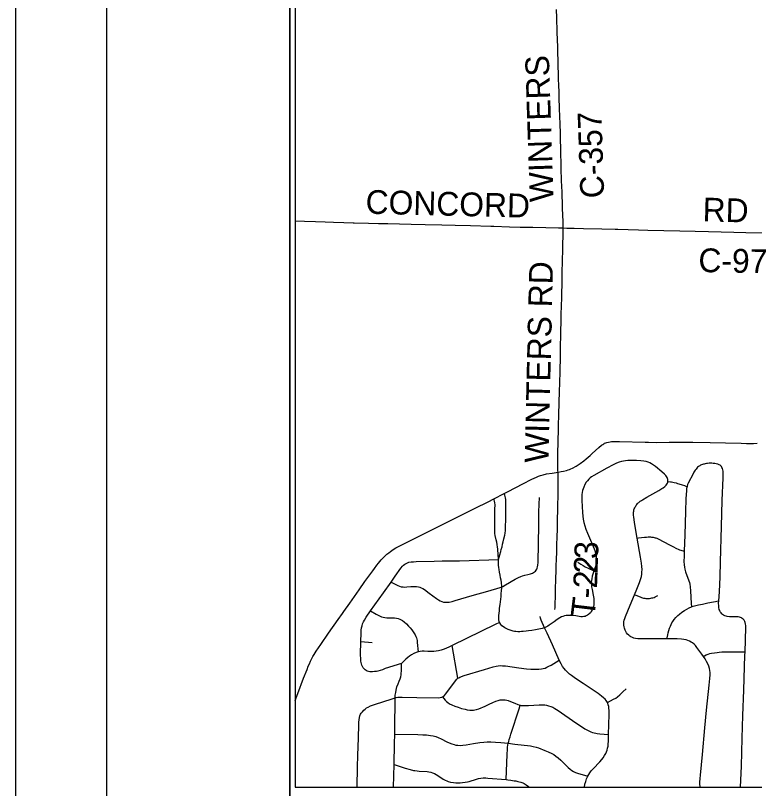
# Model space of a CAD drawing. Extents: x 1341221 to 1914484, y 79347 to 658398.
# Drawn here: x 1341221 to 1359400, y 580393 to 599399 of the extents above; entities that cross this region are included whole.
import ezdxf

# ---------------------------------------------------------------- set-up
doc = ezdxf.new("R2010")
doc.units = 0
for name, color, linetype in [('GM_X_Major_Lake_Text', 7, 'Continuous'), ('GM_X_Major_River_Text', 7, 'Continuous'), ('GM_X_Minor_Lake_Text', 7, 'Continuous'), ('GM_X_Minor_River_Text', 7, 'Continuous'), ('GM_X_State_Location', 7, 'Continuous'), ('GM_X_Township_Text', 7, 'Continuous'), ('GM_X_US_Shield', 7, 'Continuous')]:
    doc.layers.add(name, color=color, linetype=linetype)

msp = doc.modelspace()

# ---------------------------------------------------------------- linework, layer by layer
at = {"layer": 'GM_X_Minor_Lake_Text'}
for points in [[(1343471, 656148), (1347971, 656148), (1347971, 561648), (1343471, 561648)], [(1347971, 656148), (1491971, 656148), (1491971, 561648), (1347971, 561648)], [(1435650, 641695), (1348099, 641695), (1348099, 580425), (1435650, 580425)]]:
    msp.add_lwpolyline(points, close=True, dxfattribs=at)
at = {"layer": 'GM_X_Minor_River_Text'}
msp.add_lwpolyline([(1341221, 559398), (1494221, 559398), (1494221, 658398), (1341221, 658398)], close=True, dxfattribs=at)
at = {"layer": 'GM_X_State_Location'}
for points in [[(1349263, 584696), (1349300, 584748), (1349446, 584954), (1349675, 585278), (1349818, 585479), (1350009, 585745), (1350052, 585804), (1350111, 585884), (1350148, 585932), (1350181, 585974), (1350214, 586013), (1350245, 586048), (1350270, 586073), (1350305, 586108), (1350342, 586140), (1350359, 586155), (1350382, 586174), (1350402, 586189), (1350442, 586221), (1350510, 586267), (1350576, 586307), (1350626, 586335), (1351393, 586721), (1352005, 587022), (1352364, 587201), (1352525, 587284), (1352845, 587444), (1352989, 587517), (1353241, 587647), (1353340, 587698), (1353697, 587884), (1353921, 587997), (1354038, 588051), (1354089, 588072), (1354137, 588090), (1354197, 588107), (1354285, 588127), (1354422, 588149), (1354568, 588172), (1354646, 588184), (1354700, 588195), (1354775, 588213), (1354814, 588225), (1354850, 588238), (1354881, 588252), (1354924, 588272), (1355011, 588320), (1355107, 588383), (1355202, 588453), (1355262, 588502), (1355304, 588537), (1355358, 588584), (1355406, 588630), (1355566, 588775), (1355633, 588831), (1355665, 588854), (1355693, 588870), (1355712, 588880), (1355743, 588893), (1355766, 588901), (1355810, 588912), (1355845, 588918), (1355880, 588922), (1355962, 588924), (1356080, 588923), (1356707, 588906), (1356794, 588905), (1356981, 588904), (1357301, 588908), (1357570, 588908), (1357883, 588907), (1358306, 588899), (1358683, 588893), (1359067, 588883), (1359201, 588879), (1359374, 588877), (1359468, 588880)], [(1348099, 582561), (1348163, 582726), (1348308, 583102), (1348392, 583323), (1348424, 583402), (1348449, 583460), (1348478, 583521), (1348503, 583572), (1348537, 583636), (1348569, 583691), (1348620, 583772), (1348728, 583937), (1348918, 584209), (1349157, 584547), (1349263, 584696)]]:
    msp.add_lwpolyline(points, dxfattribs=at)
at = {"layer": 'GM_X_Township_Text'}
for p, q in [((1349718, 584004), (1349992, 583983)), ((1352100, 583103), (1351960, 583907))]:
    msp.add_line(p, q, dxfattribs=at)
for points in [[(1354568, 588172), (1354565, 588206), (1354561, 588243), (1354560, 588261), (1354560, 588275), (1354559, 588315), (1354559, 588347), (1354559, 588394), (1354561, 588470), (1354562, 588555), (1354564, 588656), (1354569, 588894), (1354571, 588996), (1354575, 589150), (1354581, 589377), (1354584, 589519), (1354588, 589657), (1354593, 589807), (1354597, 589956), (1354600, 590076), (1354604, 590199), (1354608, 590319), (1354613, 590465), (1354615, 590550), (1354619, 590668), (1354621, 590762), (1354624, 590903), (1354625, 591024), (1354627, 591145), (1354628, 591233), (1354630, 591319), (1354634, 591484), (1354637, 591613), (1354638, 591651), (1354644, 591855), (1354647, 592021), (1354653, 592284), (1354656, 592434), (1354659, 592583), (1354664, 592786), (1354667, 592949), (1354671, 593136), (1354674, 593301), (1354676, 593397), (1354681, 593616), (1354685, 593765), (1354689, 593991), (1354690, 594074), (1354693, 594175)], [(1358065, 580425), (1358061, 580446), (1358055, 580498), (1358054, 580550), (1358059, 580640), (1358068, 580723), (1358117, 581232), (1358179, 581882), (1358221, 582321), (1358286, 582938), (1358301, 583095), (1358306, 583185), (1358306, 583249), (1358300, 583297), (1358291, 583342), (1358272, 583402), (1358248, 583461), (1358221, 583518), (1358186, 583578), (1358145, 583640), (1358103, 583699), (1357983, 583864), (1357946, 583907), (1357911, 583943), (1357877, 583971), (1357839, 583994), (1357801, 584015), (1357755, 584034), (1357715, 584045), (1357664, 584055), (1357601, 584063), (1357493, 584069), (1357248, 584070), (1357052, 584071), (1356700, 584070), (1356611, 584069), (1356527, 584074), (1356475, 584081), (1356431, 584091), (1356394, 584104), (1356358, 584121), (1356330, 584139), (1356304, 584160), (1356277, 584189), (1356253, 584220), (1356232, 584253), (1356215, 584289), (1356199, 584332), (1356190, 584370), (1356185, 584409), (1356184, 584448), (1356187, 584487), (1356195, 584532), (1356208, 584576), (1356226, 584625), (1356343, 584902), (1356450, 585157), (1356506, 585291), (1356572, 585462), (1356595, 585531), (1356616, 585608), (1356625, 585659), (1356630, 585715), (1356632, 585778), (1356628, 585854), (1356619, 585937), (1356598, 586082), (1356516, 586550), (1356457, 586882), (1356438, 586996), (1356427, 587076), (1356425, 587108), (1356423, 587133), (1356424, 587163), (1356425, 587190), (1356429, 587215), (1356434, 587242), (1356442, 587266), (1356454, 587294), (1356466, 587319), (1356477, 587338), (1356491, 587359), (1356505, 587378), (1356522, 587398), (1356540, 587417), (1356552, 587428), (1356571, 587444), (1356588, 587457), (1356618, 587477), (1356644, 587494), (1356748, 587552), (1357043, 587718), (1357123, 587770), (1357148, 587789), (1357191, 587822), (1357222, 587850), (1357244, 587879), (1357257, 587903), (1357264, 587922), (1357267, 587940), (1357267, 587968), (1357265, 587989), (1357260, 588013), (1357251, 588038), (1357238, 588062), (1357218, 588086), (1357188, 588118), (1357122, 588178), (1356966, 588310), (1356918, 588345), (1356867, 588377), (1356824, 588400), (1356779, 588417), (1356735, 588430), (1356680, 588442), (1356602, 588451), (1356495, 588455), (1356378, 588457), (1356284, 588455), (1356229, 588451), (1356178, 588443), (1356124, 588432), (1356070, 588415), (1356003, 588388), (1355923, 588350), (1355765, 588266), (1355445, 588091), (1355392, 588057), (1355357, 588030), (1355321, 587995), (1355289, 587957), (1355262, 587921), (1355228, 587864), (1355199, 587804), (1355183, 587762), (1355169, 587718), (1355160, 587673), (1355154, 587623), (1355151, 587566), (1355151, 587471), (1355156, 587323), (1355165, 587176), (1355172, 587088), (1355183, 587012), (1355200, 586932), (1355222, 586852), (1355250, 586768), (1355290, 586667), (1355416, 586380), (1355470, 586242), (1355488, 586187), (1355501, 586130), (1355508, 586085), (1355511, 586040), (1355509, 585994), (1355505, 585949), (1355495, 585891), (1355484, 585855), (1355447, 585741), (1355429, 585685), (1355408, 585612), (1355394, 585550), (1355388, 585506), (1355385, 585456), (1355386, 585393), (1355390, 585355), (1355402, 585287), (1355432, 585143), (1355444, 585066), (1355448, 585009), (1355449, 584956), (1355445, 584913), (1355437, 584868), (1355423, 584823), (1355406, 584786), (1355384, 584746), (1355361, 584716), (1355333, 584686), (1355313, 584668), (1355288, 584651), (1355258, 584636), (1355231, 584626), (1355201, 584620), (1355164, 584616), (1355129, 584617), (1355087, 584622), (1355005, 584636), (1354936, 584645), (1354867, 584650), (1354818, 584649), (1354769, 584644), (1354725, 584636), (1354685, 584625), (1354654, 584612), (1354611, 584590), (1354546, 584547), (1354467, 584490), (1354348, 584406), (1354313, 584384), (1354279, 584365), (1354236, 584342)], [(1359053, 580425), (1359078, 580939), (1359098, 581628), (1359115, 582190), (1359139, 582815), (1359162, 583670), (1359165, 583749), (1359187, 584352), (1359186, 584397), (1359180, 584434), (1359170, 584471), (1359157, 584501), (1359141, 584528), (1359118, 584556), (1359098, 584575), (1359077, 584588), (1359053, 584599), (1359031, 584606), (1358998, 584611), (1358947, 584612), (1358903, 584612), (1358781, 584617), (1358730, 584622), (1358699, 584629), (1358665, 584640), (1358637, 584654), (1358614, 584669), (1358594, 584687), (1358575, 584710), (1358556, 584737), (1358544, 584766), (1358533, 584797), (1358524, 584840), (1358519, 584885), (1358516, 584949), (1358520, 585010), (1358536, 585230), (1358550, 585600), (1358565, 585969), (1358588, 586832), (1358607, 587472), (1358627, 588034), (1358627, 588150), (1358625, 588192), (1358618, 588232), (1358610, 588259), (1358599, 588283), (1358584, 588306), (1358569, 588325), (1358551, 588341), (1358529, 588354), (1358496, 588368), (1358455, 588378), (1358422, 588383), (1358384, 588387), (1358350, 588389), (1358314, 588389), (1358280, 588388), (1358246, 588385), (1358216, 588381), (1358189, 588377), (1358164, 588371), (1358143, 588366), (1358123, 588361), (1358097, 588351), (1358074, 588341), (1358051, 588327), (1358025, 588311), (1358000, 588290), (1357982, 588271), (1357962, 588248), (1357937, 588219), (1357923, 588196), (1357906, 588168), (1357887, 588132), (1357766, 587898), (1357752, 587865), (1357739, 587816), (1357729, 587770), (1357723, 587721), (1357711, 587514), (1357700, 587201), (1357682, 586626), (1357669, 586232), (1357665, 586109), (1357663, 585974), (1357667, 585892), (1357673, 585834), (1357682, 585784), (1357700, 585723), (1357787, 585496), (1357799, 585458), (1357809, 585416), (1357818, 585353), (1357825, 585251), (1357841, 584945), (1357846, 584862)], [(1354491, 584796), (1354493, 584841), (1354495, 584901), (1354498, 584980), (1354500, 585065), (1354502, 585159), (1354503, 585231), (1354507, 585350), (1354511, 585486), (1354514, 585584), (1354518, 585717), (1354523, 585874), (1354527, 586026), (1354533, 586208), (1354539, 586387), (1354544, 586579), (1354550, 586768), (1354553, 586894), (1354556, 587032), (1354560, 587221), (1354563, 587367), (1354567, 587584), (1354570, 587744), (1354571, 587890), (1354571, 588044), (1354571, 588075), (1354571, 588112), (1354570, 588136), (1354569, 588154), (1354568, 588172)], [(1357267, 587940), (1357329, 587935), (1357357, 587931), (1357389, 587926), (1357422, 587919), (1357472, 587905), (1357503, 587896), (1357539, 587885), (1357618, 587857), (1357673, 587839), (1357722, 587822), (1357739, 587816)], [(1350462, 585469), (1350623, 585383), (1350668, 585365), (1350711, 585354), (1350755, 585348), (1350795, 585346), (1350847, 585349), (1350947, 585357), (1351029, 585360), (1351088, 585358), (1351133, 585351), (1351166, 585343), (1351200, 585330), (1351239, 585310), (1351278, 585286), (1351397, 585199), (1351575, 585065), (1351627, 585028), (1351668, 585007), (1351710, 584989), (1351752, 584977), (1351790, 584972), (1351842, 584971), (1351887, 584976), (1351965, 584994), (1352032, 585012), (1352455, 585137), (1352843, 585248), (1353145, 585333), (1353182, 585349), (1353207, 585361), (1353272, 585398), (1353510, 585536), (1353590, 585578), (1353647, 585604), (1353691, 585620), (1353748, 585635), (1353823, 585652), (1353892, 585671), (1353937, 585687), (1353965, 585700), (1353991, 585718), (1354015, 585740), (1354030, 585761), (1354044, 585783), (1354055, 585811), (1354063, 585844), (1354070, 585882), (1354074, 585947), (1354086, 586413), (1354091, 586867), (1354097, 587187), (1354103, 587385), (1354110, 587544)], [(1353105, 586021), (1353099, 586062), (1353096, 586119), (1353093, 586176), (1353088, 586238), (1353085, 586284), (1353080, 586329), (1353070, 586390), (1353058, 586446), (1353045, 586509), (1353022, 586611), (1353015, 586661), (1353012, 586697), (1353009, 586840), (1353010, 587073), (1353012, 587187), (1353014, 587262), (1353016, 587366), (1353012, 587418), (1353006, 587458), (1352997, 587489), (1352989, 587517)], [(1353105, 586021), (1353136, 586142), (1353156, 586217), (1353169, 586268), (1353189, 586338), (1353203, 586397), (1353219, 586456), (1353237, 586530), (1353260, 586624), (1353267, 586674), (1353273, 586739), (1353276, 586795), (1353281, 587040), (1353283, 587254), (1353285, 587404), (1353282, 587501), (1353278, 587536), (1353269, 587573), (1353256, 587609), (1353241, 587647)], [(1356516, 586550), (1356544, 586553), (1356692, 586572), (1356740, 586575), (1356786, 586578), (1356816, 586578), (1356842, 586577), (1356864, 586576), (1356885, 586574), (1356909, 586570), (1356933, 586565), (1356956, 586560), (1356975, 586555), (1356996, 586546), (1357030, 586529), (1357310, 586385), (1357389, 586344), (1357480, 586297), (1357521, 586277), (1357553, 586263), (1357584, 586252), (1357611, 586244), (1357641, 586238), (1357669, 586232)], [(1353130, 584477), (1353020, 584423), (1351960, 583907), (1351881, 583871), (1351763, 583822), (1351691, 583797), (1351624, 583778), (1351569, 583767), (1351512, 583761), (1351456, 583759), (1351367, 583763), (1351270, 583768), (1351221, 583767), (1351175, 583762), (1351128, 583754), (1351075, 583735), (1351016, 583710), (1350963, 583682), (1350914, 583651), (1350872, 583618), (1350826, 583576), (1350789, 583539), (1350748, 583499), (1350712, 583470), (1350318, 583340), (1350246, 583315), (1350189, 583297), (1350136, 583282), (1350100, 583274), (1350051, 583266), (1350004, 583260), (1349968, 583260), (1349936, 583264), (1349902, 583270), (1349874, 583279), (1349848, 583292), (1349820, 583311), (1349794, 583334), (1349772, 583360), (1349754, 583393), (1349739, 583426), (1349728, 583462), (1349722, 583490), (1349717, 583523), (1349713, 583573), (1349710, 583686), (1349718, 584004), (1349721, 584210), (1349726, 584286), (1349733, 584342), (1349745, 584392), (1349759, 584438), (1349779, 584489), (1349802, 584534), (1349844, 584604), (1349955, 584763), (1350276, 585208), (1350462, 585469), (1350559, 585612), (1350698, 585810), (1350738, 585858), (1350768, 585887), (1350799, 585911), (1350828, 585929), (1350860, 585942), (1350900, 585954), (1350950, 585963), (1351009, 585970), (1351076, 585974), (1351516, 585985), (1351714, 585987), (1352142, 585990), (1353105, 586021)], [(1355213, 580425), (1355213, 580426), (1355228, 580502), (1355247, 580568), (1355268, 580628), (1355296, 580693), (1355322, 580740), (1355346, 580778), (1355384, 580828), (1355430, 580881), (1355594, 581051), (1355641, 581104), (1355677, 581151), (1355712, 581205), (1355738, 581253), (1355757, 581299), (1355771, 581334), (1355786, 581384), (1355796, 581432), (1355802, 581480), (1355806, 581557), (1355811, 581724), (1355822, 582216), (1355822, 582312), (1355817, 582372), (1355812, 582413), (1355803, 582453), (1355790, 582489), (1355782, 582508), (1355766, 582534), (1355749, 582560), (1355723, 582590), (1355687, 582625), (1355637, 582666), (1355553, 582725), (1355187, 582972), (1355043, 583068), (1354959, 583126), (1354895, 583170), (1354846, 583208), (1354804, 583246), (1354751, 583301), (1354715, 583345), (1354680, 583394), (1354641, 583462), (1354598, 583548), (1354432, 583928), (1354300, 584213), (1354236, 584342), (1354172, 584324), (1354096, 584309), (1354013, 584294), (1353925, 584281), (1353843, 584270), (1353781, 584262), (1353712, 584254), (1353667, 584250), (1353630, 584248), (1353575, 584247), (1353529, 584250), (1353496, 584254), (1353459, 584262), (1353415, 584275), (1353336, 584305), (1353260, 584341), (1353221, 584366), (1353186, 584395), (1353159, 584425), (1353134, 584464), (1353130, 584477), (1353120, 584502), (1353113, 584541), (1353111, 584594), (1353114, 584650), (1353119, 584701), (1353124, 584759), (1353130, 584824), (1353142, 584920), (1353150, 584982), (1353164, 585117), (1353171, 585179), (1353178, 585265), (1353181, 585318), (1353182, 585349), (1353182, 585361), (1353180, 585395), (1353178, 585427), (1353174, 585460), (1353165, 585515), (1353154, 585571), (1353140, 585641), (1353127, 585709), (1353116, 585779), (1353110, 585830), (1353104, 585882), (1353103, 585933), (1353105, 586021)], [(1355055, 585957), (1355128, 585907), (1355184, 585872), (1355237, 585841), (1355306, 585807), (1355447, 585741)], [(1356450, 585157), (1356476, 585147), (1356588, 585103), (1356616, 585092), (1356642, 585083), (1356671, 585075), (1356697, 585070), (1356728, 585067), (1356755, 585066), (1356785, 585066), (1356813, 585068), (1356849, 585073), (1356874, 585077), (1356898, 585084), (1356928, 585093), (1356958, 585105), (1356992, 585122), (1357021, 585140)], [(1357248, 584070), (1357253, 584097), (1357266, 584170), (1357279, 584222), (1357292, 584276), (1357311, 584338), (1357331, 584387), (1357349, 584427), (1357367, 584464), (1357387, 584499), (1357423, 584552), (1357464, 584601), (1357515, 584650), (1357553, 584683), (1357615, 584729), (1357673, 584769), (1357733, 584805), (1357789, 584836), (1357846, 584862), (1357889, 584876), (1357925, 584886), (1358024, 584908), (1358123, 584929), (1358252, 584956), (1358388, 584984), (1358439, 584994), (1358507, 585007), (1358520, 585010)], [(1349955, 584763), (1350094, 584682), (1350173, 584641), (1350225, 584618), (1350268, 584604), (1350310, 584595), (1350352, 584590), (1350414, 584589), (1350490, 584591), (1350547, 584589), (1350597, 584582), (1350635, 584573), (1350674, 584560), (1350709, 584543), (1350742, 584522), (1350781, 584492), (1350836, 584442), (1350891, 584388), (1350933, 584342), (1350969, 584296), (1351021, 584223), (1351053, 584170), (1351069, 584134), (1351083, 584098), (1351092, 584066), (1351098, 584028), (1351104, 583982), (1351128, 583754)], [(1354236, 584342), (1354155, 584535), (1354137, 584583), (1354123, 584624)], [(1358145, 583640), (1358169, 583653), (1358210, 583676), (1358257, 583696), (1358299, 583709), (1358341, 583720), (1358416, 583732), (1358482, 583740), (1358529, 583746), (1358592, 583751), (1358644, 583753), (1358690, 583755), (1358770, 583755), (1359142, 583750), (1359165, 583749)], [(1349623, 580425), (1349636, 580928), (1349645, 581208), (1349658, 581641), (1349667, 581956), (1349668, 582028), (1349673, 582085), (1349681, 582135), (1349695, 582183), (1349710, 582218), (1349726, 582245), (1349753, 582281), (1349788, 582319), (1349821, 582348), (1349857, 582375), (1349895, 582397), (1349953, 582425), (1350024, 582453), (1350073, 582470), (1350463, 582589), (1350560, 582619), (1350586, 582627), (1350629, 582637), (1350661, 582641), (1350731, 582643), (1351095, 582634), (1351620, 582626), (1351670, 582631), (1351704, 582637), (1351727, 582647), (1351748, 582663), (1351771, 582684), (1351795, 582712), (1352080, 583083), (1352100, 583103), (1352123, 583117), (1352151, 583130), (1352259, 583170), (1352754, 583323), (1352968, 583385), (1353043, 583402), (1353093, 583411), (1353151, 583415), (1353202, 583413), (1353278, 583407), (1353601, 583360), (1353791, 583337), (1353900, 583329), (1354021, 583324), (1354097, 583326), (1354160, 583332), (1354198, 583340), (1354247, 583356), (1354294, 583375), (1354343, 583399), (1354396, 583429), (1354598, 583548)], [(1350518, 580425), (1350532, 580986), (1350545, 581496), (1350550, 581729), (1350556, 582007), (1350558, 582461), (1350560, 582619), (1350564, 582686), (1350574, 582751), (1350587, 582814), (1350605, 582891), (1350630, 582963), (1350659, 583034), (1350683, 583093), (1350696, 583136), (1350706, 583186), (1350711, 583231), (1350713, 583282), (1350712, 583470)], [(1355782, 582508), (1355934, 582586), (1355985, 582616), (1356032, 582648), (1356086, 582694), (1356164, 582770), (1356242, 582842)], [(1351727, 582647), (1351761, 582603), (1351792, 582565), (1351823, 582533), (1351858, 582505), (1351899, 582479), (1351950, 582452), (1352026, 582419), (1352106, 582389), (1352190, 582364), (1352283, 582340), (1352333, 582330), (1352397, 582322), (1352447, 582321), (1352485, 582323), (1352518, 582328), (1352560, 582338), (1352615, 582354), (1352679, 582378), (1352716, 582393), (1352772, 582418), (1352873, 582466), (1352965, 582510), (1353039, 582541), (1353092, 582559), (1353139, 582570), (1353180, 582576), (1353224, 582577), (1353267, 582573), (1353305, 582567), (1353342, 582556), (1353395, 582535), (1353507, 582488), (1353577, 582459), (1353633, 582441), (1353655, 582436), (1353696, 582431), (1353766, 582430), (1353842, 582432), (1353970, 582442), (1354104, 582452), (1354187, 582452), (1354239, 582448), (1354286, 582441), (1354333, 582429), (1354386, 582411), (1354436, 582389), (1354488, 582359), (1354566, 582311), (1355003, 582012), (1355146, 581915), (1355227, 581864), (1355309, 581818), (1355344, 581800), (1355376, 581786), (1355415, 581773), (1355456, 581761), (1355492, 581752), (1355526, 581747), (1355598, 581739), (1355811, 581724)], [(1353291, 580611), (1353314, 581231), (1353321, 581358), (1353325, 581412), (1353331, 581458), (1353342, 581505), (1353352, 581545), (1353366, 581600), (1353385, 581666), (1353405, 581733), (1353606, 582352), (1353633, 582441)], [(1350550, 581729), (1351116, 581718), (1351238, 581716), (1351334, 581710), (1351429, 581700), (1351496, 581688), (1351560, 581669), (1351614, 581649), (1351690, 581615), (1351832, 581542), (1351889, 581514), (1351955, 581489), (1352010, 581472), (1352053, 581462), (1352104, 581456), (1352162, 581454), (1352226, 581457), (1352308, 581466), (1352485, 581496), (1352642, 581522), (1352738, 581533), (1352820, 581539), (1352910, 581540), (1353031, 581536), (1353158, 581526), (1353342, 581505), (1353501, 581484), (1353889, 581439), (1353958, 581428), (1354027, 581412), (1354084, 581393), (1354242, 581331), (1354325, 581297), (1354417, 581252), (1354464, 581226), (1354515, 581190), (1354570, 581147), (1354632, 581092), (1354728, 580998), (1354815, 580913), (1354868, 580867), (1354909, 580836), (1354950, 580812), (1354994, 580790), (1355047, 580770), (1355296, 580693)], [(1350532, 580986), (1350634, 580952), (1350810, 580893), (1350928, 580859), (1351010, 580838), (1351046, 580833), (1351098, 580826), (1351153, 580822), (1351345, 580811), (1351389, 580805), (1351439, 580794), (1351482, 580781), (1351526, 580762), (1351568, 580739), (1351638, 580694), (1351739, 580626), (1351791, 580597), (1351827, 580580), (1351865, 580567), (1351919, 580553), (1351991, 580542), (1352054, 580536), (1352157, 580535), (1352220, 580539), (1352285, 580547), (1352341, 580558), (1352377, 580568), (1352558, 580625), (1352611, 580638), (1352666, 580647), (1352723, 580652), (1352787, 580653), (1352841, 580649), (1353291, 580611), (1353330, 580606), (1353409, 580597), (1353484, 580586), (1353531, 580578), (1353578, 580568), (1353649, 580547), (1353700, 580529), (1353729, 580514), (1353757, 580498), (1353786, 580480), (1353838, 580443), (1353859, 580425)]]:
    msp.add_lwpolyline(points, dxfattribs=at)
at = {"layer": 'GM_X_US_Shield'}
for points in [[(1354693, 594175), (1354692, 594199), (1354692, 594253), (1354690, 594349), (1354685, 594476), (1354678, 594675), (1354673, 594816), (1354669, 594941), (1354664, 595087), (1354661, 595172), (1354654, 595369), (1354647, 595609), (1354633, 596150), (1354628, 596327), (1354623, 596485), (1354615, 596746), (1354610, 596908), (1354603, 597121), (1354595, 597375), (1354590, 597540), (1354587, 597657), (1354581, 597853), (1354578, 597970), (1354573, 598141), (1354568, 598332), (1354564, 598442), (1354558, 598624), (1354552, 598799), (1354546, 598984), (1354543, 599100), (1354539, 599237), (1354536, 599343), (1354530, 599542)], [(1348099, 594352), (1348107, 594352), (1348330, 594343), (1348597, 594333), (1348839, 594324), (1349043, 594318), (1349300, 594309), (1349530, 594303)], [(1349530, 594303), (1349549, 594302), (1349906, 594294), (1350152, 594287), (1350383, 594282), (1350670, 594275), (1350952, 594269), (1351297, 594261), (1351706, 594251), (1352038, 594242), (1352416, 594231), (1352914, 594218), (1352987, 594216), (1353369, 594204), (1353637, 594198), (1353947, 594191), (1354262, 594184), (1354576, 594177), (1354693, 594175), (1354782, 594173), (1354962, 594169), (1355195, 594164), (1355645, 594154), (1355968, 594145), (1356034, 594144), (1356291, 594136), (1356542, 594130), (1356771, 594123), (1357562, 594103), (1357935, 594094), (1358270, 594085), (1358580, 594078), (1358887, 594071), (1359182, 594064), (1359663, 594052)]]:
    msp.add_lwpolyline(points, dxfattribs=at)

# ---------------------------------------------------------------- texts
at = {"layer": 'GM_X_Major_Lake_Text'}
for s, rotation, p in [('WINTERS', 91.8579, (1354457, 594825)), ('C-357', 91.9283, (1355703, 594914)), ('CONCORD', 358.5928, (1349828, 594526)), ('RD', 358.5193, (1358117, 594337)), ('C-97', 358.9714, (1358015, 593091))]:
    msp.add_text(s, height=585, rotation=rotation, dxfattribs=at).set_placement(p)
at = {"layer": 'GM_X_Major_River_Text'}
for s, rotation, p in [('WINTERS RD', 88.6469, (1354328, 588395)), ('3', 88.2117, (1355549, 586029)), ('2', 88.147, (1355537, 585668)), ('2', 87.8898, (1355524, 585305)), ('-', 87.3588, (1355512, 585059)), ('T', 83.1806, (1355457, 584578))]:
    msp.add_text(s, height=585, rotation=rotation, dxfattribs=at).set_placement(p)

doc.saveas('drawing.dxf')
